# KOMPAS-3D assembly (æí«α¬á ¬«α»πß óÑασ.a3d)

Referenced files in D:\МОДЕЛЬ ТАНКА Т90\ДЕТАЛИ\КОРПУС\МЕТАЛЛ\КОРПУС ШТАМПОВКА\: корпус верх.m3d, люк механника.m3d
Referenced files in D:\МОДЕЛЬ ТАНКА Т90\ДЕТАЛИ\КОРПУС\МЕТАЛЛ\КОРПУС ШТАМПОВКА\ПЛАСТИК\: корпус верх пластик.m3d
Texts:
  Сборка корпус верх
